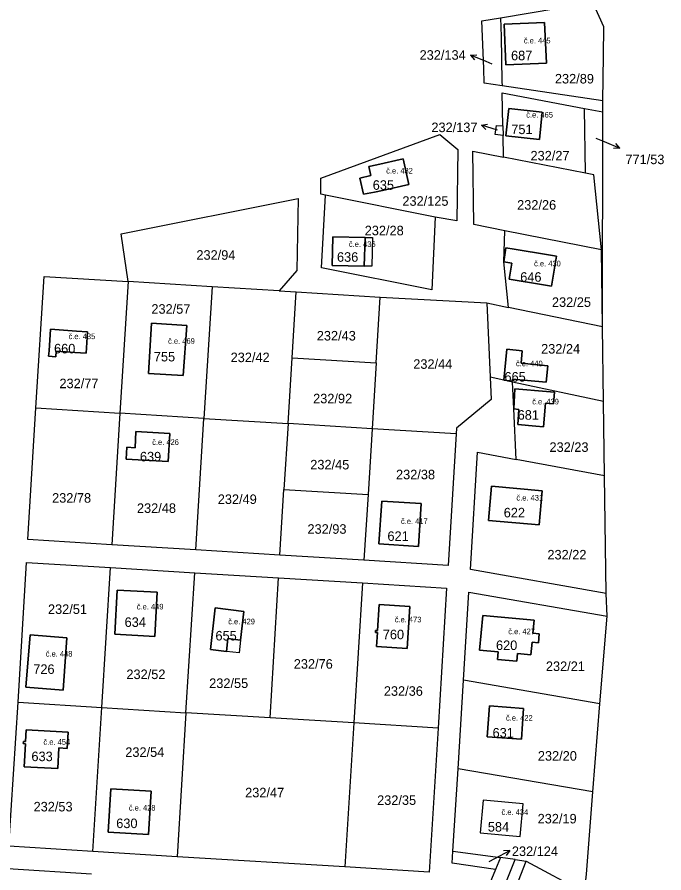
# Model space of a CAD drawing. Extents: x -887272 to -880188, y -1026687 to -1021896.
# Drawn here: x -881922.6 to -881807.4, y -1023755.1 to -1023602.5 of the extents above; entities that cross this region are included whole.
import ezdxf

# ---------------------------------------------------------------- set-up
doc = ezdxf.new("R2010")
doc.units = 0
for name, color, linetype in [('Definiční body', 7, 'Continuous'), ('Hranice parcel', 7, 'Continuous'), ('Parcelní čísla', 7, 'Continuous'), ('Polygon budovy', 7, 'Continuous'), ('Pop  PČ popisy', 7, 'Continuous'), ('Vnitřní kresba', 7, 'Continuous')]:
    doc.layers.add(name, color=color, linetype=linetype)

msp = doc.modelspace()

# ---------------------------------------------------------------- linework, layer by layer
at = {"layer": 'Hranice parcel'}
for p, q in [((-881836.44, -1023602.65), (-881826.23, -1023600.97)), ((-881818.23, -1023617.44), (-881836.19, -1023614.81)), ((-881818.26, -1023619.44), (-881818.23, -1023617.44)), ((-881821.5, -1023618.82), (-881818.26, -1023619.44)), ((-881821.3, -1023630.36), (-881821.5, -1023618.82)), ((-881818.3, -1023657.74), (-881818.26, -1023619.44)), ((-881836.04, -1023621.94), (-881836, -1023623.64)), ((-881835.92, -1023627.51), (-881836, -1023623.64)), ((-881821.3, -1023630.36), (-881835.92, -1023627.51)), ((-881848.1, -1023638.17), (-881867.63, -1023634.29)), ((-881835.87, -1023646.15), (-881835.72, -1023640.61)), ((-881818.49, -1023644.04), (-881835.72, -1023640.61)), ((-881818.3, -1023657.74), (-881818.49, -1023644.04)), ((-881835.03, -1023654.29), (-881835.87, -1023646.15)), ((-881902.81, -1023649.69), (-881904.27, -1023673.15)), ((-881887.84, -1023650.6), (-881902.81, -1023649.69)), ((-881887.84, -1023650.6), (-881889.3, -1023674.08)), ((-881875.88, -1023651.34), (-881887.84, -1023650.6)), ((-881875.88, -1023651.34), (-881872.88, -1023651.52)), ((-881873.59, -1023663.25), (-881872.88, -1023651.52)), ((-881872.88, -1023651.52), (-881857.89, -1023652.44)), ((-881858.62, -1023664.17), (-881857.89, -1023652.44)), ((-881857.89, -1023652.44), (-881838.93, -1023653.49)), ((-881838.93, -1023653.49), (-881835.03, -1023654.29)), ((-881838.93, -1023653.49), (-881838.32, -1023666.74)), ((-881818.3, -1023657.74), (-881835.03, -1023654.29)), ((-881818.1, -1023671.07), (-881818.3, -1023657.74)), ((-881874.31, -1023674.98), (-881873.59, -1023663.25)), ((-881873.59, -1023663.25), (-881858.62, -1023664.17)), ((-881858.62, -1023664.17), (-881859.34, -1023675.9)), ((-881835.89, -1023667.26), (-881838.32, -1023666.74)), ((-881834.34, -1023667.59), (-881835.89, -1023667.26)), ((-881818.1, -1023671.07), (-881834.34, -1023667.59)), ((-881817.93, -1023684.3), (-881818.1, -1023671.07)), ((-881919.24, -1023672.21), (-881904.27, -1023673.15)), ((-881904.27, -1023673.15), (-881905.73, -1023696.58)), ((-881889.3, -1023674.08), (-881904.27, -1023673.15)), ((-881890.75, -1023697.49), (-881889.3, -1023674.08)), ((-881889.3, -1023674.08), (-881874.31, -1023674.98)), ((-881874.31, -1023674.98), (-881875.05, -1023686.72)), ((-881859.34, -1023675.9), (-881874.31, -1023674.98)), ((-881859.34, -1023675.9), (-881860.07, -1023687.62)), ((-881844.35, -1023676.82), (-881859.34, -1023675.9)), ((-881817.93, -1023684.3), (-881833.67, -1023681.37)), ((-881817.63, -1023705.3), (-881817.93, -1023684.3)), ((-881875.79, -1023698.46), (-881875.05, -1023686.72)), ((-881875.05, -1023686.72), (-881860.07, -1023687.62)), ((-881860.07, -1023687.62), (-881860.81, -1023699.34)), ((-881890.75, -1023697.49), (-881905.73, -1023696.58)), ((-881875.79, -1023698.46), (-881890.75, -1023697.49)), ((-881860.81, -1023699.34), (-881875.79, -1023698.46)), ((-881907.51, -1023725.59), (-881905.94, -1023700.64)), ((-881905.94, -1023700.64), (-881890.94, -1023701.57)), ((-881892.55, -1023726.54), (-881890.94, -1023701.57)), ((-881890.94, -1023701.57), (-881876.02, -1023702.5)), ((-881877.53, -1023727.45), (-881876.02, -1023702.5)), ((-881876.02, -1023702.5), (-881861.03, -1023703.38)), ((-881861.03, -1023703.38), (-881862.57, -1023728.35)), ((-881817.47, -1023709.33), (-881817.63, -1023705.3)), ((-881818.77, -1023724.96), (-881817.47, -1023709.33)), ((-881843.99, -1023736.53), (-881843.07, -1023720.74)), ((-881818.77, -1023724.96), (-881843.07, -1023720.74)), ((-881922.43, -1023724.66), (-881907.51, -1023725.59)), ((-881909.11, -1023751.24), (-881907.51, -1023725.59)), ((-881907.51, -1023725.59), (-881892.55, -1023726.54)), ((-881819.99, -1023740.61), (-881818.77, -1023724.96)), ((-881892.55, -1023726.54), (-881894.1, -1023752.21)), ((-881877.53, -1023727.45), (-881892.55, -1023726.54)), ((-881862.57, -1023728.35), (-881877.53, -1023727.45)), ((-881862.57, -1023728.35), (-881864.2, -1023754)), ((-881847.59, -1023729.26), (-881862.57, -1023728.35)), ((-881844.94, -1023751.18), (-881843.99, -1023736.53)), ((-881819.99, -1023740.61), (-881843.99, -1023736.53)), ((-881894.1, -1023752.21), (-881909.11, -1023751.24)), ((-881864.2, -1023754), (-881894.1, -1023752.21)), ((-881845.1, -1023753.36), (-881844.94, -1023751.18)), ((-881844.94, -1023751.18), (-881836.45, -1023752.35)), ((-881836.45, -1023752.35), (-881837.34, -1023754.48)), ((-881833.85, -1023752.71), (-881836.45, -1023752.35)), ((-881837.34, -1023754.48), (-881845.1, -1023753.36)), ((-881841.17, -1023770.99), (-881833.85, -1023752.71)), ((-881839.01, -1023771.53), (-881831.92, -1023752.98)), ((-881833.85, -1023752.71), (-881831.92, -1023752.98)), ((-881831.92, -1023752.98), (-881821.47, -1023758.6))]:
    msp.add_line(p, q, dxfattribs=at)
for points in [[(-881818.23, -1023617.44), (-881818.12, -1023609.45), (-881818.05, -1023604.28), (-881820, -1023599.95)], [(-881836.19, -1023614.81), (-881839.36, -1023614.34), (-881839.46, -1023611.7), (-881839.79, -1023603.19), (-881836.44, -1023602.65)], [(-881836.44, -1023602.65), (-881836.37, -1023606.01), (-881836.2, -1023614.01), (-881836.19, -1023614.81)], [(-881828.6, -1023603.51), (-881828.29, -1023610.72), (-881835.51, -1023611.03), (-881835.82, -1023603.82), (-881828.6, -1023603.51)], [(-881836.04, -1023621.94), (-881836.16, -1023616.01), (-881821.5, -1023618.82)], [(-881835.51, -1023623.73), (-881834.99, -1023618.82), (-881829.02, -1023619.5), (-881829.53, -1023624.36), (-881835.51, -1023623.73)], [(-881836, -1023623.64), (-881837.4, -1023623.47), (-881837.2, -1023621.84), (-881836.04, -1023621.94)], [(-881867.63, -1023634.29), (-881868.47, -1023634.08), (-881868.49, -1023631.24), (-881847.25, -1023623.48), (-881844.07, -1023626.16), (-881844.27, -1023638.83), (-881848.1, -1023638.17)], [(-881835.72, -1023640.61), (-881841.21, -1023639.51), (-881841.42, -1023626.42), (-881835.92, -1023627.51)], [(-881853.8, -1023627.8), (-881852.78, -1023632.37), (-881857.48, -1023633.42), (-881858.9, -1023633.73), (-881860.85, -1023634.09), (-881861.52, -1023631.22), (-881859.55, -1023630.8), (-881859.91, -1023629.17), (-881858.49, -1023628.85), (-881853.8, -1023627.8)], [(-881818.49, -1023644.04), (-881819.83, -1023630.65), (-881821.3, -1023630.36)], [(-881902.81, -1023649.69), (-881904.03, -1023641.17), (-881872.52, -1023634.89), (-881872.78, -1023647.68), (-881875.88, -1023651.34)], [(-881848.1, -1023638.17), (-881848.73, -1023651.13), (-881868.37, -1023647.25), (-881867.63, -1023634.29)], [(-881859.4, -1023646.94), (-881860.77, -1023646.91), (-881866.43, -1023646.79), (-881866.32, -1023641.7), (-881860.59, -1023641.82), (-881859.28, -1023641.85), (-881859.4, -1023646.94)], [(-881835.87, -1023646.15), (-881835.49, -1023643.64), (-881834.06, -1023643.88), (-881827.89, -1023644.9), (-881826.5, -1023645.13), (-881827.4, -1023650.5), (-881828.78, -1023650.27), (-881834.95, -1023649.25), (-881834.47, -1023646.39), (-881835.87, -1023646.15)], [(-881919.24, -1023672.21), (-881917.8, -1023648.78), (-881902.81, -1023649.69)], [(-881893.01, -1023666.44), (-881899.19, -1023666.04), (-881898.62, -1023657.09), (-881892.36, -1023657.53), (-881893.01, -1023666.44)], [(-881910.31, -1023662.46), (-881912.31, -1023662.32), (-881915.61, -1023662.09), (-881915.68, -1023663.09), (-881916.98, -1023663), (-881916.91, -1023662), (-881916.63, -1023658.19), (-881912.04, -1023658.52), (-881910.04, -1023658.66), (-881910.31, -1023662.46)], [(-881835.89, -1023667.26), (-881835.32, -1023661.73), (-881832.63, -1023662.02), (-881832.77, -1023664.21), (-881828.02, -1023664.67), (-881828.32, -1023667.62), (-881834.34, -1023667.07), (-881834.35, -1023667.41), (-881835.89, -1023667.26)], [(-881838.32, -1023666.74), (-881838.11, -1023670.71), (-881844.32, -1023675.83), (-881844.35, -1023676.82)], [(-881833.67, -1023681.37), (-881834.11, -1023672.38), (-881834.34, -1023667.59)], [(-881833.91, -1023668.8), (-881828.26, -1023669.28), (-881826.85, -1023669.41), (-881827.03, -1023671.49), (-881828.42, -1023671.37), (-881828.78, -1023675.55), (-881830.19, -1023675.43), (-881833.4, -1023675.15), (-881833.17, -1023672.48), (-881834.11, -1023672.38), (-881833.91, -1023668.8)], [(-881905.73, -1023696.58), (-881920.68, -1023695.66), (-881919.24, -1023672.21)], [(-881895.67, -1023681.74), (-881903.17, -1023681.35), (-881903.05, -1023679.22), (-881901.56, -1023679.3), (-881901.41, -1023676.41), (-881895.41, -1023676.73), (-881895.67, -1023681.74)], [(-881844.35, -1023676.82), (-881845.82, -1023700.28), (-881860.81, -1023699.34)], [(-881817.63, -1023705.3), (-881841.82, -1023700.99), (-881840.58, -1023680.07), (-881833.67, -1023681.37)], [(-881838.07, -1023686.14), (-881829.02, -1023686.98), (-881829.58, -1023693.01), (-881838.61, -1023692.25), (-881838.07, -1023686.14)], [(-881857.61, -1023688.83), (-881850.62, -1023689.23), (-881851.1, -1023696.9), (-881858.12, -1023696.42), (-881857.61, -1023688.83)], [(-881922.43, -1023724.66), (-881920.91, -1023699.74), (-881905.94, -1023700.64)], [(-881861.03, -1023703.38), (-881846.07, -1023704.32), (-881847.59, -1023729.26)], [(-881904.74, -1023704.66), (-881897.61, -1023705.05), (-881898.04, -1023712.93), (-881905.17, -1023712.54), (-881904.74, -1023704.66)], [(-881843.07, -1023720.74), (-881842.08, -1023705.02), (-881817.47, -1023709.33)], [(-881882.17, -1023708.46), (-881882.77, -1023713.58), (-881883.04, -1023715.87), (-881885.3, -1023715.6), (-881888.16, -1023715.26), (-881887.29, -1023707.86), (-881882.17, -1023708.46)], [(-881852.62, -1023707.59), (-881853.07, -1023715.07), (-881858.55, -1023714.73), (-881858.39, -1023712.23), (-881858.75, -1023712.2), (-881858.73, -1023711.85), (-881858.37, -1023711.87), (-881858.08, -1023707.25), (-881852.62, -1023707.59)], [(-881833.55, -1023717.32), (-881837.01, -1023717.03), (-881836.89, -1023715.68), (-881840.18, -1023715.38), (-881839.62, -1023709.21), (-881830.49, -1023710.02), (-881830.7, -1023712.34), (-881829.58, -1023712.44), (-881829.7, -1023714.08), (-881830.85, -1023713.98), (-881831.05, -1023716.21), (-881833.42, -1023715.99), (-881833.55, -1023717.32)], [(-881914.41, -1023722.5), (-881921.01, -1023721.96), (-881920.24, -1023712.63), (-881913.72, -1023713.17), (-881914.41, -1023722.5)], [(-881909.11, -1023751.24), (-881924.05, -1023750.31), (-881922.43, -1023724.66)], [(-881832.35, -1023725.76), (-881832.74, -1023731.26), (-881838.85, -1023730.81), (-881838.42, -1023725.29), (-881832.35, -1023725.76)], [(-881847.59, -1023729.26), (-881849.18, -1023754.92), (-881864.2, -1023754)], [(-881921.34, -1023736.16), (-881921.11, -1023732.06), (-881921.49, -1023732.04), (-881921.47, -1023731.66), (-881921.09, -1023731.68), (-881920.97, -1023729.56), (-881913.52, -1023729.98), (-881913.68, -1023732.89), (-881915.13, -1023732.81), (-881915.33, -1023736.49), (-881921.34, -1023736.16)], [(-881906.38, -1023747.81), (-881905.91, -1023740.07), (-881898.71, -1023740.51), (-881899.18, -1023748.25), (-881906.38, -1023747.81)], [(-881821.47, -1023758.6), (-881821.15, -1023755.32), (-881819.99, -1023740.61)], [(-881839.53, -1023742.09), (-881840.1, -1023747.91), (-881832.99, -1023748.61), (-881832.42, -1023742.78), (-881839.53, -1023742.09)], [(-881925.8, -1023779.26), (-881924.27, -1023754.29), (-881909.32, -1023755.23)], [(-881837.34, -1023754.48), (-881838.77, -1023757.91), (-881839.5, -1023759.51)]]:
    msp.add_lwpolyline(points, dxfattribs=at)
at = {"layer": 'Polygon budovy'}
for points in [[(-881835.82, -1023603.82), (-881835.51, -1023611.03), (-881828.29, -1023610.72), (-881828.6, -1023603.51)], [(-881835.51, -1023623.73), (-881829.53, -1023624.36), (-881829.02, -1023619.5), (-881834.99, -1023618.82)], [(-881861.52, -1023631.22), (-881860.85, -1023634.09), (-881858.9, -1023633.73), (-881857.48, -1023633.42), (-881852.78, -1023632.37), (-881853.8, -1023627.8), (-881858.49, -1023628.85), (-881859.91, -1023629.17), (-881859.55, -1023630.8)], [(-881866.43, -1023646.79), (-881860.77, -1023646.91), (-881860.59, -1023641.82), (-881866.32, -1023641.7)], [(-881835.49, -1023643.64), (-881835.87, -1023646.15), (-881834.47, -1023646.39), (-881834.95, -1023649.25), (-881828.78, -1023650.27), (-881827.4, -1023650.5), (-881826.5, -1023645.13), (-881827.89, -1023644.9), (-881834.06, -1023643.88)], [(-881893.01, -1023666.44), (-881892.36, -1023657.53), (-881898.62, -1023657.09), (-881899.19, -1023666.04)], [(-881916.63, -1023658.19), (-881916.91, -1023662), (-881916.98, -1023663), (-881915.68, -1023663.09), (-881915.61, -1023662.09), (-881912.31, -1023662.32), (-881910.31, -1023662.46), (-881910.04, -1023658.66), (-881912.04, -1023658.52)], [(-881835.32, -1023661.73), (-881835.89, -1023667.26), (-881834.35, -1023667.41), (-881834.34, -1023667.07), (-881828.32, -1023667.62), (-881828.02, -1023664.67), (-881832.77, -1023664.21), (-881832.63, -1023662.02)], [(-881833.91, -1023668.8), (-881834.11, -1023672.38), (-881833.17, -1023672.48), (-881833.4, -1023675.15), (-881830.19, -1023675.43), (-881828.78, -1023675.55), (-881828.42, -1023671.37), (-881827.03, -1023671.49), (-881826.85, -1023669.41), (-881828.26, -1023669.28)], [(-881903.17, -1023681.35), (-881895.67, -1023681.74), (-881895.41, -1023676.73), (-881901.41, -1023676.41), (-881901.56, -1023679.3), (-881903.05, -1023679.22)], [(-881829.02, -1023686.98), (-881838.07, -1023686.14), (-881838.61, -1023692.25), (-881829.58, -1023693.01)], [(-881857.61, -1023688.83), (-881858.12, -1023696.42), (-881851.1, -1023696.9), (-881850.62, -1023689.23)], [(-881904.74, -1023704.66), (-881905.17, -1023712.54), (-881898.04, -1023712.93), (-881897.61, -1023705.05)], [(-881887.29, -1023707.86), (-881888.16, -1023715.26), (-881885.3, -1023715.6), (-881885.03, -1023713.32), (-881882.77, -1023713.58), (-881882.17, -1023708.46)], [(-881858.75, -1023712.2), (-881858.39, -1023712.23), (-881858.55, -1023714.73), (-881853.07, -1023715.07), (-881852.62, -1023707.59), (-881858.08, -1023707.25), (-881858.37, -1023711.87), (-881858.73, -1023711.85)], [(-881839.62, -1023709.21), (-881840.18, -1023715.38), (-881836.89, -1023715.68), (-881837.01, -1023717.03), (-881833.55, -1023717.32), (-881833.42, -1023715.99), (-881831.05, -1023716.21), (-881830.85, -1023713.98), (-881829.7, -1023714.08), (-881829.58, -1023712.44), (-881830.7, -1023712.34), (-881830.49, -1023710.02)], [(-881921.01, -1023721.96), (-881914.41, -1023722.5), (-881913.72, -1023713.17), (-881920.24, -1023712.63)], [(-881838.42, -1023725.29), (-881838.85, -1023730.81), (-881832.74, -1023731.26), (-881832.35, -1023725.76)], [(-881921.49, -1023732.04), (-881921.11, -1023732.06), (-881921.34, -1023736.16), (-881915.33, -1023736.49), (-881915.13, -1023732.81), (-881913.68, -1023732.89), (-881913.52, -1023729.98), (-881920.97, -1023729.56), (-881921.09, -1023731.68), (-881921.47, -1023731.66)], [(-881905.91, -1023740.07), (-881906.38, -1023747.81), (-881899.18, -1023748.25), (-881898.71, -1023740.51)], [(-881839.53, -1023742.09), (-881840.1, -1023747.91), (-881832.99, -1023748.61), (-881832.42, -1023742.78)]]:
    msp.add_lwpolyline(points, close=True, dxfattribs=at)
at = {"layer": 'Pop  PČ popisy'}
for p, q in [((-881841.8, -1023609.31), (-881840.69, -1023609.24)), ((-881839.04, -1023610.48), (-881841.8, -1023609.31)), ((-881841.8, -1023609.31), (-881841.08, -1023610.16)), ((-881837.97, -1023610.94), (-881839.04, -1023610.48)), ((-881839.88, -1023621.82), (-881838.78, -1023621.64)), ((-881837.01, -1023622.7), (-881839.88, -1023621.82)), ((-881839.88, -1023621.82), (-881839.07, -1023622.59)), ((-881819.46, -1023624.09), (-881817.97, -1023624.72)), ((-881817.97, -1023624.72), (-881815.21, -1023625.89)), ((-881815.21, -1023625.89), (-881815.93, -1023625.04)), ((-881815.21, -1023625.89), (-881816.33, -1023625.96)), ((-881837.47, -1023752.5), (-881834.82, -1023751.09)), ((-881834.82, -1023751.09), (-881835.94, -1023751.12)), ((-881834.82, -1023751.09), (-881835.47, -1023752)), ((-881838.5, -1023753.04), (-881837.47, -1023752.5))]:
    msp.add_line(p, q, dxfattribs=at)
at = {"layer": 'Vnitřní kresba'}
for p, q in [((-881860.59, -1023641.82), (-881860.77, -1023646.91)), ((-881885.03, -1023713.32), (-881885.3, -1023715.6)), ((-881882.77, -1023713.58), (-881885.03, -1023713.32))]:
    msp.add_line(p, q, dxfattribs=at)

# ---------------------------------------------------------------- texts
at = {"layer": 'Definiční body'}
for s, p in [('č.e. 445', (-881832.31, -1023607.23)), ('č.e. 465', (-881831.88, -1023620.44)), ('č.e. 432', (-881856.84, -1023630.42)), ('č.e. 436', (-881863.48, -1023643.5)), ('č.e. 430', (-881830.48, -1023646.97)), ('č.e. 435', (-881913.43, -1023659.94)), ('č.e. 469', (-881895.69, -1023660.77)), ('č.e. 440', (-881833.71, -1023664.78)), ('č.e. 439', (-881830.82, -1023671.57)), ('č.e. 426', (-881898.53, -1023678.79)), ('č.e. 431', (-881833.63, -1023688.71)), ('č.e. 417', (-881854.2, -1023692.9)), ('č.e. 449', (-881901.27, -1023708.12)), ('č.e. 473', (-881855.31, -1023710.42)), ('č.e. 429', (-881884.98, -1023710.77)), ('č.e. 427', (-881835.08, -1023712.53)), ('č.e. 448', (-881917.49, -1023716.52)), ('č.e. 422', (-881835.49, -1023727.95)), ('č.e. 454', (-881917.9, -1023732.24)), ('č.e. 428', (-881902.69, -1023743.97)), ('č.e. 434', (-881836.29, -1023744.73))]:
    msp.add_text(s, height=1, dxfattribs=at).set_placement(p)
at = {"layer": 'Parcelní čísla'}
for s, p in [('232/134', (-881850.88, -1023610.14)), ('687', (-881834.59, -1023610.23)), ('232/89', (-881826.77, -1023614.37)), ('232/137', (-881848.78, -1023623.04)), ('751', (-881834.54, -1023623.39)), ('232/27', (-881831.12, -1023628.09)), ('771/53', (-881814.21, -1023628.75)), ('635', (-881859.23, -1023633.32)), ('232/125', (-881853.95, -1023636.17)), ('232/26', (-881833.5, -1023636.86)), ('232/28', (-881860.66, -1023641.43)), ('232/94', (-881890.65, -1023645.79)), ('636', (-881865.6, -1023646.15)), ('646', (-881832.95, -1023649.71)), ('232/25', (-881827.3, -1023654.19)), ('232/57', (-881898.67, -1023655.41)), ('232/43', (-881869.2, -1023660.18)), ('660', (-881916.01, -1023662.48)), ('232/24', (-881829.23, -1023662.51)), ('755', (-881898.23, -1023663.91)), ('232/42', (-881884.55, -1023664.04)), ('232/44', (-881852.01, -1023665.23)), ('232/77', (-881915.05, -1023668.68)), ('665', (-881835.76, -1023667.5)), ('232/92', (-881869.85, -1023671.38)), ('681', (-881833.41, -1023674.3)), ('232/23', (-881827.74, -1023680.03)), ('639', (-881900.71, -1023681.73)), ('232/45', (-881870.36, -1023683.16)), ('232/38', (-881855.08, -1023684.92)), ('232/78', (-881916.36, -1023689.09)), ('232/49', (-881886.84, -1023689.32)), ('232/48', (-881901.24, -1023690.91)), ('622', (-881835.89, -1023691.71)), ('232/93', (-881870.86, -1023694.63)), ('621', (-881856.61, -1023695.9)), ('232/22', (-881828.11, -1023699.21)), ('232/51', (-881917.09, -1023708.92)), ('634', (-881903.44, -1023711.23)), ('655', (-881887.25, -1023713.65)), ('760', (-881857.44, -1023713.43)), ('620', (-881837.27, -1023715.35)), ('232/76', (-881873.3, -1023718.68)), ('726', (-881919.71, -1023719.61)), ('232/52', (-881903.12, -1023720.53)), ('232/21', (-881828.38, -1023719.09)), ('232/55', (-881888.37, -1023722.12)), ('232/36', (-881857.25, -1023723.51)), ('631', (-881837.88, -1023730.95)), ('633', (-881920.04, -1023735.16)), ('232/54', (-881903.32, -1023734.4)), ('232/20', (-881829.81, -1023735.07)), ('232/47', (-881881.96, -1023741.61)), ('232/35', (-881858.45, -1023742.96)), ('232/53', (-881919.66, -1023744.12)), ('232/19', (-881829.85, -1023746.26)), ('630', (-881904.93, -1023747.09)), ('584', (-881838.72, -1023747.72)), ('232/124', (-881834.44, -1023752.07))]:
    msp.add_text(s, height=1.7, dxfattribs=at).set_placement(p)

doc.saveas('drawing.dxf')
